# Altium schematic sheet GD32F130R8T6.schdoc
size 127 x 101 mm
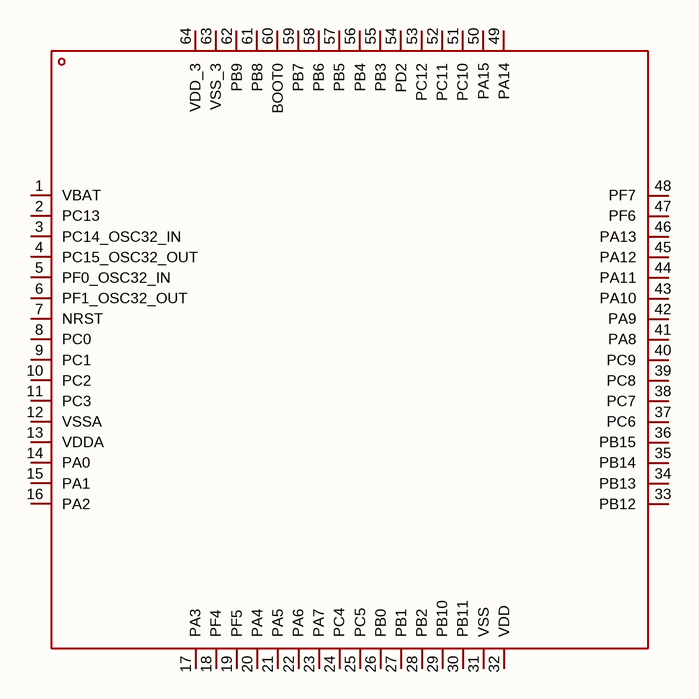
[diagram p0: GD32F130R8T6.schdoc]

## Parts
U?  gd32f130r8t6  [LQFP-64_L10.0-W10.0-P0.50-LS12.0-BL]  (value not drawn)

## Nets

Not connected (* = marked no-connect by the designer): U? 1(VBAT) 2(PC13) 3(PC14_OSC32_IN) 4(PC15_OSC32_OUT) 5(PF0_OSC32_IN) 6(PF1_OSC32_OUT) 7(NRST) 8(PC0) 9(PC1) 10(PC2) 11(PC3) 12(VSSA) 13(VDDA) 14(PA0) 15(PA1) 16(PA2) 17(PA3) 18(PF4) 19(PF5) 20(PA4) 21(PA5) 22(PA6) 23(PA7) 24(PC4) 25(PC5) 26(PB0) 27(PB1) 28(PB2) 29(PB10) 30(PB11) 31(VSS) 32(VDD) 33(PB12) 34(PB13) 35(PB14) 36(PB15) 37(PC6) 38(PC7) 39(PC8) 40(PC9) 41(PA8) 42(PA9) 43(PA10) 44(PA11) 45(PA12) 46(PA13) 47(PF6) 48(PF7) 49(PA14) 50(PA15) 51(PC10) 52(PC11) 53(PC12) 54(PD2) 55(PB3) 56(PB4) 57(PB5) 58(PB6) 59(PB7) 60(BOOT0) 61(PB8) 62(PB9) 63(VSS_3) 64(VDD_3)

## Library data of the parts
U? = gd32f130r8t6: CPU内核:ARM Cortex-M3;CPU最大主频:72MHz;; Manufacturer: GigaDevice(兆易创新); AddInBom: yes; ModelId: cd9de06618c44fcf82654c43a457f83c; ModelName: LQFP-64_L10.0-W10.0-H1.4-LS12.0-P0.50; ModelTransform: 472.441,472.441,0,0,0,0,0,0.465,0; CPU Maximum Speed: 72MHz; Program Storage Size: 64KB; Program Memory Type: FLASH; Number of I/O: 55; ADC (Bit): 12bit; Voltage - Supply: 2.6V~3.6V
